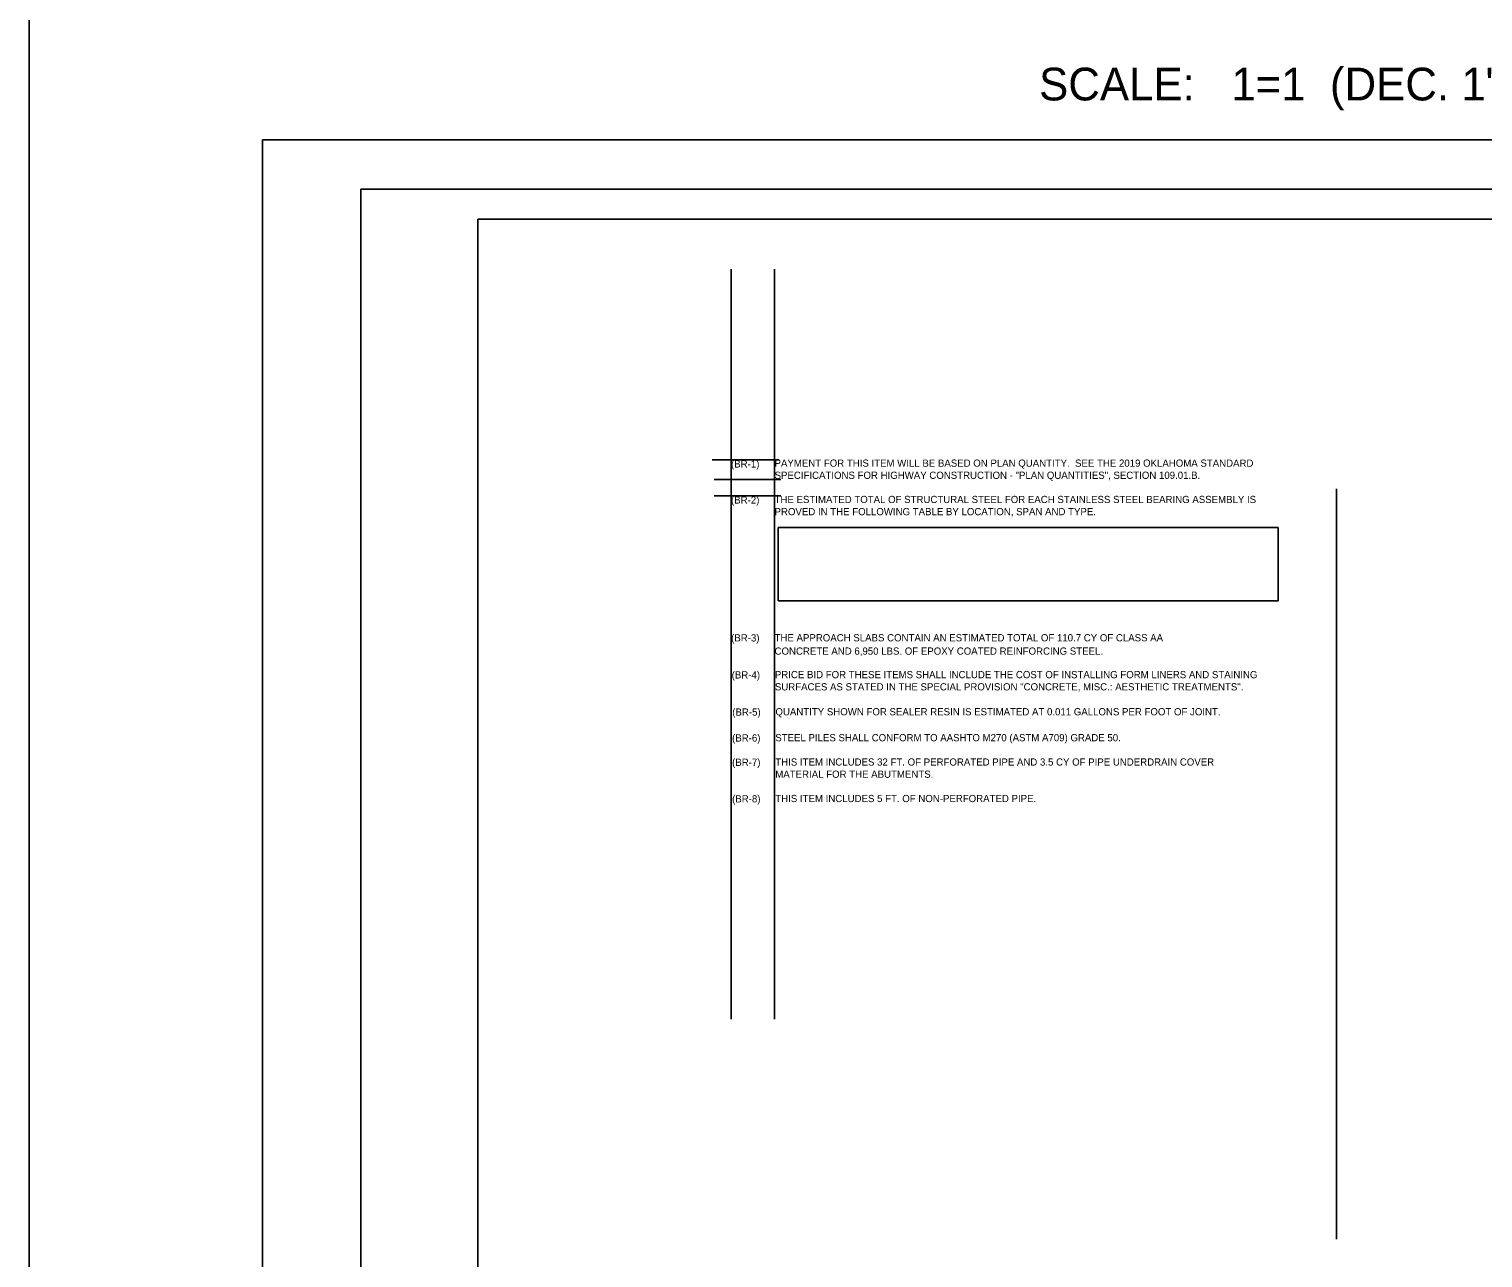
# Model space of a CAD drawing. Extents: x 12312.5 to 12355.9, y 579 to 640.5.
# Drawn here: x 12312.48 to 12336.68, y 589.98 to 610.44 of the extents above; entities that cross this region are included whole.
import ezdxf

# ---------------------------------------------------------------- set-up
doc = ezdxf.new("R2010")
doc.units = 0
for name, color, linetype in [('PTX_37_TXTS', 7, 'Continuous'), ('S', 7, 'Continuous'), ('SHT_Plot_Shape_Full', 7, 'Continuous'), ('SHT_Plot_Shape_Half', 7, 'Continuous'), ('SHT_Sheet_Border', 7, 'Continuous'), ('T', 7, 'Continuous')]:
    doc.layers.add(name, color=color, linetype=linetype)

msp = doc.modelspace()

# ---------------------------------------------------------------- linework, layer by layer
at = {"layer": 'Defpoints'}
for p, q in [((12324.161, 593.954), (12324.161, 606.446)), ((12324.886, 606.446), (12324.886, 593.954)), ((12324.963, 603.269), (12323.847, 603.269)), ((12324.993, 602.944), (12323.878, 602.944)), ((12324.993, 602.67), (12323.878, 602.67)), ((12334.24, 590.293), (12334.24, 602.785))]:
    msp.add_line(p, q, dxfattribs=at)
at = {"layer": 'S'}
msp.add_lwpolyline([(12355.912, 640.488), (12312.476, 640.488), (12312.476, 579.031), (12355.912, 579.031)], close=True, dxfattribs=at)
at = {"layer": 'SHT_Plot_Shape_Full'}
msp.add_lwpolyline([(12316.36, 608.6), (12352.36, 608.6), (12352.36, 584.6), (12316.36, 584.6)], close=True, dxfattribs=at)
at = {"layer": 'SHT_Plot_Shape_Half'}
msp.add_lwpolyline([(12317.998, 607.775), (12351.998, 607.775), (12351.998, 585.775), (12317.998, 585.775)], close=True, dxfattribs=at)
at = {"layer": 'SHT_Sheet_Border'}
msp.add_lwpolyline([(12351.448, 586.275), (12319.948, 586.275), (12319.948, 607.275), (12351.448, 607.275)], close=True, dxfattribs=at)
at = {"layer": 'T'}
msp.add_lwpolyline([(12324.947, 600.92), (12333.267, 600.92), (12333.267, 602.142), (12324.947, 602.142)], close=True, dxfattribs=at)

# ---------------------------------------------------------------- texts
at = {"layer": 'PTX_37_TXTS'}
for s, p in [('THE APPROACH SLABS CONTAIN AN ESTIMATED TOTAL OF 110.7 CY OF CLASS AA ', (12324.886, 600.247)), ('CONCRETE AND 6,950 LBS. OF EPOXY COATED REINFORCING STEEL. ', (12324.886, 600.025)), ('THIS ITEM INCLUDES 32 FT. OF PERFORATED PIPE AND 3.5 CY OF PIPE UNDERDRAIN COVER ', (12324.898, 598.178)), ('MATERIAL FOR THE ABUTMENTS.', (12324.898, 597.975)), ('THIS ITEM INCLUDES 5 FT. OF NON-PERFORATED PIPE.', (12324.898, 597.57))]:
    msp.add_text(s, height=0.12005, dxfattribs=at).set_placement(p)
at = {"layer": 'S'}
msp.add_text('SCALE:   1=1  (DEC. 1" = 1\')', height=0.54513, dxfattribs=at).set_placement((12329.289, 609.255))
at = {"layer": 'T'}
for s, p in [('(BR-1)', (12324.161, 603.141)), ('PAYMENT FOR THIS ITEM WILL BE BASED ON PLAN QUANTITY.  SEE THE 2019 OKLAHOMA STANDARD ', (12324.886, 603.155)), ('SPECIFICATIONS FOR HIGHWAY CONSTRUCTION - "PLAN QUANTITIES", SECTION 109.01.B.', (12324.886, 602.953)), ('(BR-2)', (12324.161, 602.541)), ('THE ESTIMATED TOTAL OF STRUCTURAL STEEL FOR EACH STAINLESS STEEL BEARING ASSEMBLY IS ', (12324.886, 602.55)), ('PROVED IN THE FOLLOWING TABLE BY LOCATION, SPAN AND TYPE.', (12324.886, 602.347)), ('(BR-3)', (12324.163, 600.245)), ('(BR-4)', (12324.172, 599.628)), ('PRICE BID FOR THESE ITEMS SHALL INCLUDE THE COST OF INSTALLING FORM LINERS AND STAINING ', (12324.891, 599.633)), ('SURFACES AS STATED IN THE SPECIAL PROVISION "CONCRETE, MISC.: AESTHETIC TREATMENTS".', (12324.891, 599.43)), ('(BR-5)', (12324.182, 599.01)), ('QUANTITY SHOWN FOR SEALER RESIN IS ESTIMATED AT 0.011 GALLONS PER FOOT OF JOINT.', (12324.901, 599.015)), ('(BR-6)', (12324.179, 598.578)), ('STEEL PILES SHALL CONFORM TO AASHTO M270 (ASTM A709) GRADE 50.', (12324.898, 598.583)), ('(BR-7)', (12324.179, 598.173)), ('(BR-8)', (12324.179, 597.565))]:
    msp.add_text(s, height=0.12, dxfattribs=at).set_placement(p)

doc.saveas('drawing.dxf')
